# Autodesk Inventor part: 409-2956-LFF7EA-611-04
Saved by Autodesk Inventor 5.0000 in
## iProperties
Created: 2010-06
Part Number: 409-2956-LFF7EA-611-04
Cost Center: 0 lbmass
Material: A36 STEEL PLATE
Document SubType Name: Sheet Metal
Designer: S. Boerckel
Authority: 0 in^3
Mass: 29753.3 g
Surface Area: 6312.89 cm^2
Volume: 3785.41 cm^3
Density: 7.86 g/cm^3
Flat Pattern Width: 26.67 cm
Flat Pattern Length: 111.76 cm
Flat Pattern Area: 2980.64 cm^2
Sheet Metal Rule: 1/2"Thk
Sheet Metal Width: 16.0000 in
Sheet Metal Length: 80.0000 in^2
Description: PUMP FOOT PLATE
User Status: BURN
SaveDate: 2008-01-15
SaveTime: 10:24
FileName: Sheet Metal
Wide: =<Flat Pattern Width>cm
Length: =<Flat Pattern Length>cm
Thickness: 0.5000 in
SMR: =<Sheet Metal Rule> - <Material>
Author: S. Boerckel
Revision Number: 0
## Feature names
1. Plate1
